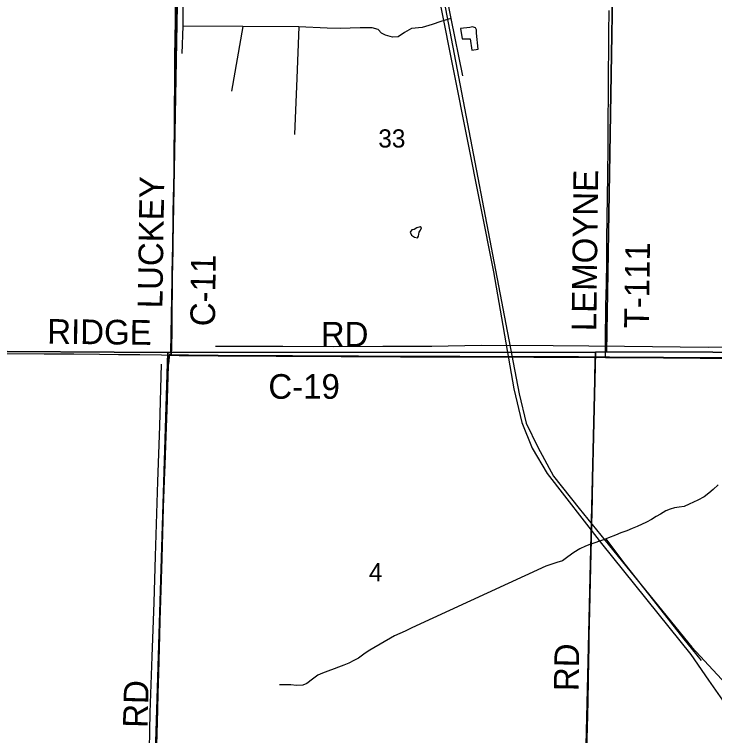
# Model space of a CAD drawing. Extents: x -8.3 to 42.1, y 0 to 22.
# Drawn here: x 3.551 to 5.164, y 17.442 to 19.103 of the extents above; entities that cross this region are included whole.
import ezdxf

# ---------------------------------------------------------------- set-up
doc = ezdxf.new("R2010")
doc.units = 0
for name, color, linetype in [('GM_X_County_Road', 7, 'Continuous'), ('GM_X_County_Road_Text', 7, 'Continuous'), ('GM_X_Minor_Lake', 7, 'Continuous'), ('GM_X_Minor_River', 7, 'Continuous'), ('GM_X_Rail_Line', 7, 'Continuous'), ('GM_X_Section', 7, 'Continuous'), ('GM_X_Section_Text', 7, 'Continuous'), ('GM_X_Township_Road', 7, 'Continuous'), ('GM_X_Township_Road_Text', 7, 'Continuous')]:
    doc.layers.add(name, color=color, linetype=linetype)

msp = doc.modelspace()

# ---------------------------------------------------------------- linework, layer by layer
at = {"layer": 'GM_X_County_Road'}
for p, q in [((3.9079, 18.3179), (3.9125, 18.3178)), ((4.8885, 18.3129), (4.9123, 18.3127))]:
    msp.add_line(p, q, dxfattribs=at)
for points in [[(3.9125, 18.3178), (3.9126, 18.3243), (3.9128, 18.3293), (3.9129, 18.3387), (3.9136, 18.3698), (3.9139, 18.4226), (3.9144, 18.4661), (3.9149, 18.5127), (3.9158, 18.5531), (3.9171, 18.6463), (3.9189, 18.7394), (3.9192, 18.7736), (3.9194, 18.7954), (3.9197, 18.8326), (3.9201, 18.8917), (3.9205, 18.9382), (3.9209, 18.9724), (3.9208, 18.9849), (3.9209, 19.0035), (3.9215, 19.047), (3.9219, 19.0874), (3.9222, 19.1247)], [(3.4054, 18.3223), (3.4174, 18.3222), (3.4702, 18.3219), (3.5199, 18.3217), (3.6194, 18.3209), (3.6878, 18.3206), (3.7468, 18.32), (3.7904, 18.3196), (3.8401, 18.319), (3.8898, 18.3182), (3.9079, 18.3179)], [(3.8757, 17.3226), (3.877, 17.3706), (3.879, 17.4452), (3.8806, 17.5011), (3.8816, 17.5384), (3.8831, 17.5849), (3.8856, 17.6719), (3.8863, 17.7061), (3.8879, 17.7527), (3.8907, 17.849), (3.8925, 17.908), (3.8942, 17.967), (3.8964, 18.0294), (3.8977, 18.0647), (3.9001, 18.1317), (3.9019, 18.1908), (3.9046, 18.2684), (3.9056, 18.2932), (3.9067, 18.3032), (3.9076, 18.314), (3.9079, 18.3179)], [(3.9125, 18.3178), (3.9302, 18.3174), (3.952, 18.3171), (4.0203, 18.3165), (4.0763, 18.3159), (4.154, 18.3155), (4.1913, 18.3154), (4.2379, 18.3152), (4.3032, 18.3148), (4.3436, 18.3148), (4.4399, 18.3143), (4.4648, 18.3143), (4.5114, 18.314), (4.5767, 18.3142), (4.6979, 18.3137), (4.7476, 18.3135), (4.7974, 18.3133), (4.8502, 18.313), (4.8885, 18.3129)], [(4.9123, 18.3127), (4.9217, 18.3127), (5.0025, 18.3122), (5.046, 18.3119), (5.13, 18.3112), (5.1921, 18.3111), (5.2356, 18.311), (5.332, 18.3111), (5.3724, 18.3114), (5.3933, 18.3114)]]:
    msp.add_lwpolyline(points, dxfattribs=at)
at = {"layer": 'GM_X_Minor_Lake'}
for p, q in [((4.6045, 19.0202), (4.6193, 19.0225)), ((4.4777, 18.6108), (4.4715, 18.6075))]:
    msp.add_line(p, q, dxfattribs=at)
for points in [[(4.6193, 19.0225), (4.6153, 19.0594), (4.6151, 19.067), (4.6126, 19.0716), (4.6062, 19.0737), (4.5997, 19.0727), (4.5785, 19.0698), (4.582, 19.0466), (4.601, 19.0461), (4.6045, 19.0202)], [(4.4715, 18.6075), (4.4666, 18.6065), (4.4623, 18.6013), (4.4659, 18.5944), (4.4722, 18.5897), (4.479, 18.588), (4.4818, 18.5917), (4.4835, 18.6012), (4.4863, 18.6057), (4.4883, 18.6109), (4.4857, 18.6133), (4.4777, 18.6108)]]:
    msp.add_lwpolyline(points, dxfattribs=at)
at = {"layer": 'GM_X_Minor_River'}
for points in [[(3.937, 19.0125), (3.9394, 19.0758), (3.9399, 19.3122), (3.9425, 19.4328), (3.9426, 19.5747)], [(4.4724, 19.4966), (4.5037, 19.3532), (4.5294, 19.2308), (4.5563, 19.0931), (4.583, 18.9612)], [(4.5563, 19.0931), (4.533, 19.0861), (4.5132, 19.0797), (4.4903, 19.0723), (4.4652, 19.0703), (4.4498, 19.0608), (4.4345, 19.0513), (4.4219, 19.0501), (4.4058, 19.0546), (4.3968, 19.059), (4.389, 19.0676), (4.3747, 19.0713), (4.3471, 19.072), (4.3009, 19.0705), (4.2714, 19.0712), (4.2063, 19.0739), (4.0772, 19.0744), (3.9394, 19.0758)], [(4.0772, 19.0744), (4.0508, 18.9259)], [(4.2063, 19.0739), (4.2011, 18.9556), (4.1963, 18.826)], [(5.3686, 18.1021), (5.373, 18.2005), (5.3738, 18.3083), (5.3747, 18.3314), (5.3707, 18.3368), (5.3688, 18.3369), (5.3601, 18.3359), (5.1491, 18.3357), (4.9564, 18.3374), (4.7921, 18.3395), (4.6259, 18.3401), (4.5126, 18.3379), (4.3993, 18.338), (4.2857, 18.3373), (4.1695, 18.3378), (4.0142, 18.3374)], [(3.8788, 16.6293), (3.8711, 16.6256), (3.8618, 16.6248), (3.8536, 16.6266), (3.8475, 16.6386), (3.8412, 16.6577), (3.8413, 16.6922), (3.8444, 16.7434), (3.8481, 16.8625), (3.8518, 16.9671), (3.8529, 17.0711), (3.8581, 17.203), (3.861, 17.3677), (3.8634, 17.4951), (3.8685, 17.624), (3.8727, 17.7484), (3.8761, 17.8546), (3.8811, 18.0272), (3.8862, 18.1546), (3.8894, 18.2972)], [(5.1716, 18.0191), (5.1603, 18.0083), (5.1506, 18.0002), (5.1394, 17.9918), (5.1252, 17.9842), (5.1053, 17.9748), (5.0938, 17.969), (5.0824, 17.9681), (5.071, 17.9661), (5.0611, 17.9629), (5.0515, 17.9594), (5.0389, 17.9517), (5.0289, 17.9459), (5.0181, 17.9393), (5.007, 17.9335), (4.9855, 17.9234), (4.9736, 17.9184), (4.9618, 17.913), (4.948, 17.9084), (4.9354, 17.903), (4.919, 17.8973), (4.9079, 17.8926), (4.8983, 17.8891), (4.888, 17.8859), (4.8765, 17.8816), (4.8666, 17.8777), (4.8536, 17.8716), (4.8394, 17.8632), (4.8255, 17.8533), (4.8131, 17.8441), (4.8002, 17.8402), (4.7864, 17.836), (4.7746, 17.8321), (4.4662, 17.69), (4.4512, 17.6821), (4.4267, 17.6716), (4.3695, 17.6381), (4.3587, 17.6312), (4.3437, 17.6201), (4.3325, 17.6143), (4.321, 17.6085), (4.3096, 17.6035), (4.2977, 17.5996), (4.2874, 17.5953)], [(4.9132, 17.8949), (4.9572, 17.8368), (5.0229, 17.7529), (5.0931, 17.6639), (5.1324, 17.6147)], [(4.2874, 17.5953), (4.2725, 17.5904), (4.2606, 17.5857), (4.2499, 17.581), (4.2372, 17.5719), (4.2248, 17.5615), (4.2153, 17.5576), (4.2005, 17.5572), (4.1873, 17.5583), (4.1717, 17.5583), (4.1615, 17.5589)]]:
    msp.add_lwpolyline(points, dxfattribs=at)
at = {"layer": 'GM_X_Rail_Line'}
for points in [[(4.1842, 20.9), (4.2824, 20.3978), (4.5315, 19.127), (4.6541, 18.5101), (4.7015, 18.2399), (4.7193, 18.1628), (4.7437, 18.1035), (4.7782, 18.045), (4.9031, 17.884), (5.1089, 17.6286), (5.1497, 17.5693), (5.1874, 17.5157), (5.2262, 17.4447), (5.2601, 17.3769), (5.294, 17.2671), (5.315, 17.167), (5.3312, 17.0685), (5.3428, 16.9248)], [(4.4602, 20.9), (4.4279, 19.896), (4.4279, 19.7141), (4.5329, 19.1719), (4.7134, 18.2287), (4.7298, 18.1615), (4.7562, 18.1061), (4.7924, 18.0389), (4.852, 17.9646), (5.1115, 17.6457), (5.209, 17.5403), (5.4439, 17.3636), (5.6263, 17.2359), (5.6901, 17.1722)]]:
    msp.add_lwpolyline(points, dxfattribs=at)
at = {"layer": 'GM_X_Section'}
for points in [[(2.9241, 19.3359), (3.9295, 19.335), (3.9115, 18.3241), (3.9047, 18.3241), (2.9164, 18.3298), (2.9226, 18.6969)], [(4.9315, 19.3303), (4.9147, 18.3251), (4.8893, 18.3249), (3.9115, 18.3241), (3.9295, 19.335)], [(5.9346, 19.331), (5.9121, 18.3219), (5.8932, 18.3221), (4.9147, 18.3251), (4.9315, 19.3303)], [(2.9069, 18.3295), (2.9164, 18.3298), (3.9047, 18.3241), (3.8739, 17.3266), (2.8735, 17.321)], [(3.9115, 18.3241), (4.8893, 18.3249), (4.866, 17.3546), (3.8739, 17.3266), (3.9047, 18.3241)], [(4.9147, 18.3251), (5.8932, 18.3221), (5.8682, 17.3386), (5.431, 17.3522), (4.866, 17.3546), (4.8893, 18.3249)]]:
    msp.add_lwpolyline(points, close=True, dxfattribs=at)
at = {"layer": 'GM_X_Township_Road'}
msp.add_line((4.8885, 18.3129), (4.9123, 18.3127), dxfattribs=at)
for points in [[(3.8768, 17.3711), (3.8788, 17.4457), (3.8804, 17.5016), (3.8814, 17.5389), (3.8828, 17.5855), (3.8853, 17.6725), (3.8861, 17.7067), (3.8877, 17.7532), (3.8904, 17.8496), (3.8923, 17.9086), (3.8939, 17.9676), (3.8961, 18.03), (3.8975, 18.0652), (3.8998, 18.1323), (3.9017, 18.1913), (3.9043, 18.269), (3.9054, 18.2938), (3.9064, 18.3037), (3.9074, 18.3146), (3.9077, 18.3184), (3.9123, 18.3183), (3.9124, 18.3248), (3.9125, 18.3299), (3.9126, 18.3393), (3.9133, 18.3703), (3.9137, 18.4232), (3.9141, 18.4666), (3.9146, 18.5132), (3.9156, 18.5536), (3.9169, 18.6468), (3.9186, 18.74), (3.9189, 18.7742), (3.9191, 18.7959), (3.9194, 18.8332), (3.9199, 18.8922), (3.9203, 18.9388), (3.9206, 18.973), (3.9206, 18.9854), (3.9206, 19.004), (3.9213, 19.0475), (3.9217, 19.0879), (3.922, 19.1252)], [(3.922, 19.1252), (3.9217, 19.0879), (3.9213, 19.0475), (3.9206, 19.004), (3.9206, 18.9854), (3.9206, 18.973), (3.9203, 18.9388), (3.9199, 18.8922), (3.9194, 18.8332), (3.9191, 18.7959), (3.9189, 18.7742), (3.9186, 18.74), (3.9169, 18.6468), (3.9156, 18.5536), (3.9146, 18.5132), (3.9141, 18.4666), (3.9137, 18.4232), (3.9133, 18.3703), (3.9126, 18.3393), (3.9125, 18.3299), (3.9124, 18.3248), (3.9123, 18.3183), (3.93, 18.3179), (3.9517, 18.3177), (4.0201, 18.317), (4.0761, 18.3165), (4.1538, 18.316), (4.1911, 18.3159), (4.2377, 18.3158), (4.3029, 18.3153), (4.3434, 18.3153), (4.4397, 18.3148), (4.4646, 18.3148), (4.5112, 18.3146), (4.5765, 18.3147), (4.6977, 18.3143), (4.7474, 18.3141), (4.7972, 18.3138), (4.85, 18.3136), (4.8883, 18.3134), (4.912, 18.3133), (4.9215, 18.3133), (5.0023, 18.3128), (5.0458, 18.3125), (5.1297, 18.3118), (5.1919, 18.3117)], [(4.9123, 18.3127), (4.9123, 18.3205), (4.9124, 18.3484), (4.9135, 18.4318), (4.9143, 18.4822), (4.9151, 18.5331), (4.9156, 18.586), (4.9177, 18.7308), (4.9185, 18.7998), (4.9186, 18.8421), (4.9188, 18.8775), (4.9189, 18.8987), (4.919, 18.9167), (4.9192, 18.9323), (4.9192, 18.9447), (4.9192, 18.959), (4.9195, 18.9845), (4.9198, 19.0069), (4.92, 19.021), (4.92, 19.0386), (4.9204, 19.076), (4.9206, 19.0944), (4.9208, 19.1112)], [(5.1919, 18.3117), (5.1297, 18.3118), (5.0458, 18.3125), (5.0023, 18.3128), (4.9215, 18.3133), (4.912, 18.3133), (4.8883, 18.3134), (4.85, 18.3136), (4.7972, 18.3138), (4.7474, 18.3141), (4.6977, 18.3143), (4.5765, 18.3147), (4.5112, 18.3146), (4.4646, 18.3148), (4.4397, 18.3148), (4.3434, 18.3153), (4.3029, 18.3153), (4.2377, 18.3158), (4.1911, 18.3159), (4.1538, 18.316), (4.0761, 18.3165), (4.0201, 18.317), (3.9517, 18.3177), (3.93, 18.3179), (3.9123, 18.3183), (3.9077, 18.3184), (3.9074, 18.3146), (3.9064, 18.3037), (3.9054, 18.2938), (3.9043, 18.269), (3.9017, 18.1913), (3.8998, 18.1323), (3.8975, 18.0652), (3.8961, 18.03), (3.8939, 17.9676), (3.8923, 17.9086), (3.8904, 17.8496), (3.8877, 17.7532), (3.8861, 17.7067), (3.8853, 17.6725), (3.8828, 17.5855), (3.8814, 17.5389), (3.8804, 17.5016), (3.8788, 17.4457), (3.8768, 17.3711)], [(4.8682, 17.3477), (4.8683, 17.3535), (4.869, 17.3883), (4.8703, 17.4343), (4.8714, 17.4877), (4.8721, 17.5219), (4.8731, 17.5692), (4.8737, 17.6152), (4.8744, 17.6456), (4.8751, 17.6711), (4.8763, 17.7283), (4.8771, 17.7637), (4.8792, 17.8626), (4.8799, 17.8918), (4.8811, 17.9272), (4.8824, 17.9869), (4.8834, 18.0391), (4.8844, 18.105), (4.8861, 18.1864), (4.8867, 18.2156), (4.8879, 18.2678), (4.8884, 18.3026), (4.8885, 18.3129)]]:
    msp.add_lwpolyline(points, dxfattribs=at)

# ---------------------------------------------------------------- texts
at = {"layer": 'GM_X_County_Road_Text'}
for s, rotation, p in [('LUCKEY', 89.1551, (3.8918, 18.4254)), ('C-11', 89.324, (4.0129, 18.3841)), ('RIDGE', 359.3517, (3.6263, 18.3442)), ('RD', 0, (4.2567, 18.3375)), ('C-19', 0, (4.1359, 18.2173)), ('RD', 88.5117, (3.8577, 17.4589))]:
    msp.add_text(s, height=0.05682, rotation=rotation, dxfattribs=at).set_placement(p)
at = {"layer": 'GM_X_Section_Text'}
for s, height, p in [('33', 0.04186, (4.3892, 18.796)), ('4', 0.0419, (4.3675, 17.7972))]:
    msp.add_text(s, height=height, rotation=0, dxfattribs=at).set_placement(p)
at = {"layer": 'GM_X_Township_Road_Text'}
for s, rotation, p in [('LEMOYNE', 89.2965, (4.891, 18.3727)), ('T-111', 89.1587, (5.012, 18.3792)), ('RD', 89.0116, (4.8502, 17.5437))]:
    msp.add_text(s, height=0.05682, rotation=rotation, dxfattribs=at).set_placement(p)

doc.saveas('drawing.dxf')
